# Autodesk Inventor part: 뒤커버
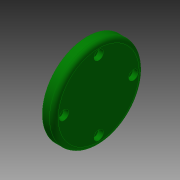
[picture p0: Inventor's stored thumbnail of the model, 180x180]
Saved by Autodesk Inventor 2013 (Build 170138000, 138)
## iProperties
Created: 2015-09
Part Number: 뒤커버
Material: 알루미늄 6061
Document SubType Name: Modeling
Designer: mduedu
Density: 2.71 g/cm^3
Mass: 54.0417 g
Surface Area: 84.9688 cm^2
Volume: 19.9416 cm^3
Author: mduedu
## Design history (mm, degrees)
sketch "스케치1"
  geometry: L1 (-15.5, 47)-(-15.5, 78); L2 (-15.5, 78)-(-23.5, 78); L3 (-23.5, 78)-(-23.5, 67); L4 (-27.5, 67)-(-27.5, 47); L5 (-79.5, 39.5)-(-79.5, 54.5) reference; L6 (48.5, 54.5)-(48.5, 39.5) reference; L7 (-79.5, 47)-(48.5, 47); L8 (-23.5, 67)-(-27.5, 67); L9 (-27.5, 47)-(-15.5, 47); 1 further point
  constraints: 14 end point, 4 midpoint, 3 parallel, 1 collinear, 1 point on line, 1 vertical
  dimensions: "d6" = 62 diameter of L2 L7; "d7" = 8 distance of L1.end L2.end; "d8" = 40 diameter of L3.end L7; "d32" = 12 distance between parallel lines of L1 L4
revolve "회전1" sketch "스케치1" stored, may be unused: angle "d4" = 90 deg
sketch "스케치4"
  geometry: C1 r 31 at (0, 0) reference; 2 further points
  constraints: 1 coincident
hole "구멍3" sketch "스케치4" at (0, 0) diameter "d33" = 33; stored, may be unused: countersink angle "d37" = 90 deg, drill point angle "d39" = 0 deg; dims "d34" = 6, "d35" = 4, "d36" = 2, "d38" = 5
fillet "모깎기4" dims "d56" = 3
chamfer "모따기2" distance "d41" = 1; stored, may be unused: second distance "d42" = 2, angle "d43" = 45 deg
sketch "스케치5" dims "d44" = 48
  geometry: C1 r 31 at (0, 0) reference; 6 further points
  constraints: 2 vertical alignment, 1 coincident, 7 other
  dimensions: "d47" = 360 deg dimension on C1.centre point (0, -24) (derived)
sketch "스케치6"
  geometry: C1 r 28 at (0, 0) reference; A1 r 24 centre (0, 0) between (24, 0) and (0, 24); 2 further points
  constraints: 4 point on circle, 2 horizontal alignment, 2 vertical alignment, 1 centre point, 1 coincident
  dimensions: "d57" = 48 diameter of A1
hole "구멍4" sketch "스케치6" at (24, 0), (0, 24), (-24, 0), (0, -24) diameter "d49" = 3.4; stored, may be unused: countersink angle "d53" = 90 deg, drill point angle "d55" = 0 deg; dims "d50" = 6, "d51" = 6.5, "d52" = 3.4, "d54" = 8
node "솔리드1"
node "참조1"
node "참조2"
